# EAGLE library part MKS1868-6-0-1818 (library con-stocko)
Serie MKS 1850 Lötstifte In-line, Raster 2.5 mm, Stiftwannen, stehend, mit Rastlasche Source: http://www.stocko.de/de/index.php?seite=ka_rfk2_mks1850.html&rubrik=Katalog+-+RFK+2 rfk_1850.pdf
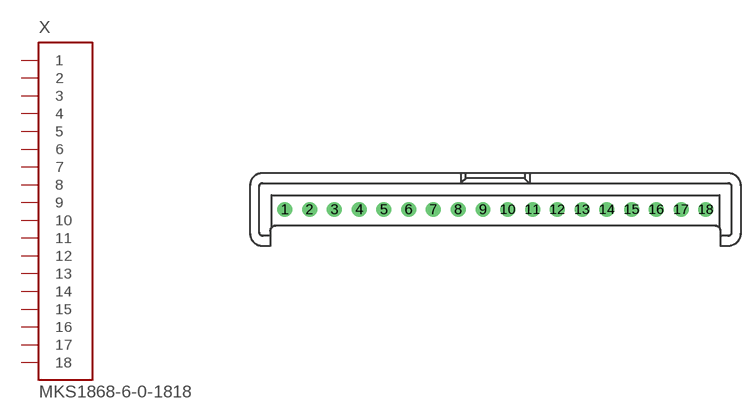
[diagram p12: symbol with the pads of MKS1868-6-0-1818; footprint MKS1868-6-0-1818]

Designator prefix X

## MKS1868-6-0-1818 (OC_FARNELL: unknown; OC_NEWARK: unknown)  [MKS1868-6-0-1818]
1  1  in
2  2  in
3  3  in
4  4  in
5  5  in
6  6  in
7  7  in
8  8  in
9  9  in
10  10  in
11  11  in
12  12  in
13  13  in
14  14  in
15  15  in
16  16  in
17  17  in
18  18  in

## Footprint MKS1868-6-0-1818 (pad centres in mm)
Serie MKS 1850 Lötstifte In-line, Raster 2.5 mm, Stiftwannen, stehend, mit Rastlasche Source: http://www.stocko.de/de/index.php?seite=ka_rfk2_mks1850.html&rubrik=Katalog+-+RFK+2 rfk_1850.pdf
drill 1 pad 1.422 round: 1 -21.25,0; 2 -18.75,0; 3 -16.25,0; 4 -13.75,0; 5 -11.25,0; 6 -8.75,0; 7 -6.25,0; 8 -3.75,0; 9 -1.25,0; 10 1.25,0; 11 3.75,0; 12 6.25,0; 13 8.75,0; 14 11.25,0; 15 13.75,0; 16 16.25,0; 17 18.75,0; 18 21.25,0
